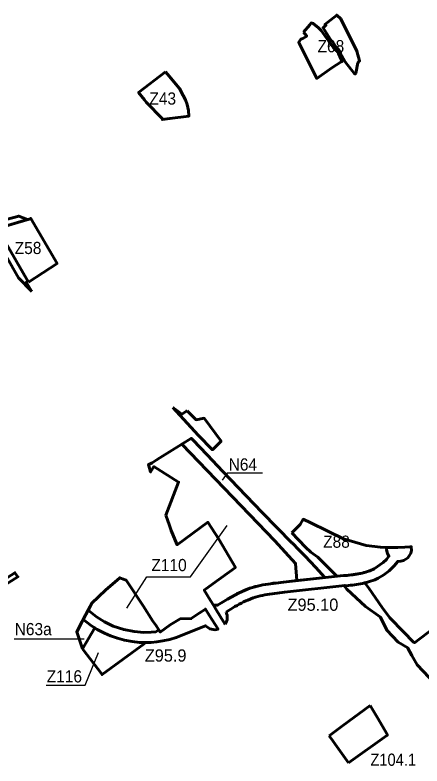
# Model space of a CAD drawing. Extents: x -650277 to -643420, y -1073980 to -1066720.
# Drawn here: x -647523 to -646722, y -1072547 to -1071070 of the extents above; entities that cross this region are included whole.
import ezdxf

# ---------------------------------------------------------------- set-up
doc = ezdxf.new("R2010")
doc.units = 0
doc.header["$LTSCALE"] = 9.6
for name, color, linetype, lineweight in [('15', 7, 'Continuous', 60), ('24', 7, 'Continuous', 60), ('30', 7, 'Continuous', 60), ('35', 7, 'Continuous', 60), ('42', 7, 'Continuous', 60), ('45', 7, 'Continuous', 60), ('60', 7, 'Continuous', 60), ('63', 7, 'Continuous', 25), ('9', 7, 'Continuous', 60)]:
    doc.layers.add(name, color=color, linetype=linetype, lineweight=lineweight)

msp = doc.modelspace()

# ---------------------------------------------------------------- linework, layer by layer
at = {"layer": '15'}
for points in [[(-647498.271, -1071593.544), (-647558.654, -1071489.738), (-647498.8, -1071471.94), (-647515.87, -1071465.25), (-647576.471, -1071481.091), (-647568.35, -1071496.656), (-647516.376, -1071586.89), (-647490.561, -1071613.609)], [(-647490.561, -1071613.609), (-647493.6, -1071608.5), (-647501.11, -1071595.45), (-647498.271, -1071593.544)]]:
    msp.add_lwpolyline(points, dxfattribs=at)
at = {"layer": '24'}
for points in [[(-647226.41, -1072054.11), (-647219.64, -1072074.29), (-647216.23, -1072084.14), (-647204.78, -1072110.92), (-647204.38, -1072111.87), (-647143.76, -1072067.69), (-647122.33, -1072101.34), (-647089.54, -1072156.53), (-647134.17, -1072188.95), (-647151.05, -1072201.21), (-647138.65, -1072221.5), (-647133, -1072230.754), (-647124.81, -1072231.168), (-647104.989, -1072219.005), (-647082.249, -1072206.591), (-647060.973, -1072197.439), (-647035.515, -1072191.104), (-647010.148, -1072187.308), (-646995.137, -1072185.597), (-646968.503, -1072182.672), (-646971.283, -1072148.82), (-647011.762, -1072104.502), (-647194.903, -1071913.941), (-647238.1, -1071941), (-647245.71, -1071945.77), (-647253.67, -1071950.76), (-647261.12, -1071954.82), (-647259.7, -1071957.06), (-647256.53, -1071968.64), (-647253.85, -1071964.38), (-647249.92, -1071958.12), (-647201.53, -1071988.71)], [(-647390.58, -1072316.75), (-647366.505, -1072275.41), (-647372.858, -1072271.363), (-647383.813, -1072263.219), (-647389.072, -1072258.845), (-647391.3, -1072263.04), (-647401.88, -1072283.4)], [(-647390.58, -1072316.75), (-647351.86, -1072367.52), (-647269.52, -1072307.17), (-647265.793, -1072304.439), (-647271.395, -1072304.452), (-647278.108, -1072304.147), (-647292.715, -1072302.646), (-647308.157, -1072299.786), (-647321.953, -1072296.073), (-647335.382, -1072291.341), (-647347.369, -1072286.111), (-647361.521, -1072278.584), (-647366.505, -1072275.41)]]:
    msp.add_lwpolyline(points, close=True, dxfattribs=at)
msp.add_arc((-646767.624, -1072120.384), 24.428, 264.28146, 264.89913, dxfattribs=at)
at = {"layer": '30'}
for points in [[(-646824.42, -1072428.58), (-646878.91, -1072468.54), (-646905.18, -1072487.8)], [(-646867.283, -1072540.984), (-646791.569, -1072487.198), (-646790.354, -1072486.136), (-646810.77, -1072451.09), (-646824.42, -1072428.58)], [(-646905.18, -1072487.8), (-646898.1, -1072498.02), (-646893.64, -1072504.45), (-646867.283, -1072540.984)]]:
    msp.add_lwpolyline(points, dxfattribs=at)
at = {"layer": '35'}
msp.add_lwpolyline([(-647246.563, -1072270.214), (-647251.85, -1072262.12), (-647271.38, -1072232.23), (-647304.32, -1072181.81), (-647310.33, -1072179.58), (-647317.33, -1072176.99), (-647345.42, -1072201.58), (-647372.1, -1072226.89), (-647375.551, -1072233.387), (-647379.422, -1072240.675), (-647363.317, -1072253.632), (-647347.382, -1072263.623), (-647330.032, -1072271.935), (-647309.416, -1072278.875), (-647288.769, -1072283.003), (-647269.579, -1072284.489), (-647255.671, -1072284.192), (-647246.206, -1072283.328), (-647240.55, -1072279.42)], close=True, dxfattribs=at)
at = {"layer": '42'}
msp.add_lwpolyline([(-647011.762, -1072104.502), (-646971.283, -1072148.82), (-646968.503, -1072182.672), (-646942.928, -1072179.864), (-646913.373, -1072176.618), (-646931.653, -1072156.802), (-646942.78, -1072144.74), (-646952.48, -1072134.22), (-646964.8, -1072121.83), (-646977.59, -1072108.96), (-646978.45, -1072108.09), (-647036.8, -1072048.41), (-647068.31, -1072015.68), (-647114.59, -1071967.77), (-647145.38, -1071935), (-647173.14, -1071905.45), (-647174.57, -1071904.06), (-647176.32, -1071902.3), (-647194.903, -1071913.941)], close=True, dxfattribs=at)
msp.add_lwpolyline([(-647637.082, -1072251.377), (-647611.306, -1072234.563), (-647589.02, -1072219.66), (-647517.51, -1072174.98), (-647523.71, -1072167.071), (-647616.719, -1072226.154), (-647642.504, -1072242.974), (-647800.2, -1072343.615)], dxfattribs=at)
at = {"layer": '45'}
msp.add_lwpolyline([(-646643.55, -1072233.5), (-646737.449, -1072305.019), (-646738.951, -1072303.49), (-646758.684, -1072283.41), (-646785.958, -1072255.505), (-646800.76, -1072235.668), (-646826.893, -1072197.582), (-646832.718, -1072189.697), (-646834.279, -1072186.818), (-646833.373, -1072186.562), (-646835.538, -1072187.097), (-646839.556, -1072187.988), (-646843.569, -1072188.789), (-646847.575, -1072189.507), (-646851.567, -1072190.155), (-646855.545, -1072190.741), (-646859.506, -1072191.276), (-646863.448, -1072191.771), (-646867.371, -1072192.234), (-646871.271, -1072192.675), (-646874.517, -1072192.471), (-646875.509, -1072192.58), (-646870.21, -1072199.51), (-646833.75, -1072233.32), (-646803.98, -1072254.74), (-646791.59, -1072279.78), (-646769.24, -1072303.65), (-646750.58, -1072315.02), (-646750.12, -1072315.82), (-646742.32, -1072329.62), (-646731.82, -1072348.2), (-646696.83, -1072385.81)], dxfattribs=at)
at = {"layer": '60'}
msp.add_line((-646978.602, -1072088.66), (-646951.95, -1072116.84), dxfattribs=at)
for points in [[(-647184.81, -1071848.61), (-647185.62, -1071849.12), (-647194.96, -1071854.93), (-647205.62, -1071847.24), (-647212.66, -1071842.15)], [(-647212.66, -1071842.15), (-647163.08, -1071896.13), (-647135.015, -1071925.145), (-647135.015, -1071925.145)], [(-647135.015, -1071925.145), (-647135.015, -1071925.145), (-647117.709, -1071908.3), (-647151.07, -1071863.08), (-647167.15, -1071866.22), (-647184.81, -1071848.61)], [(-646790.432, -1072129.195), (-646791.977, -1072122.305), (-646791.84, -1072117.172), (-646804.27, -1072116.98), (-646832.01, -1072113.66), (-646876.83, -1072100.12), (-646941.054, -1072069.172), (-646956.04, -1072061.95), (-646962.041, -1072072.379), (-646978.602, -1072088.66)], [(-646951.95, -1072116.84), (-646941.45, -1072126.84), (-646927.14, -1072136.74), (-646891.05, -1072172.79), (-646890.044, -1072174.056), (-646876.712, -1072172.592), (-646873.495, -1072172.799), (-646862.09, -1072171.444), (-646840.102, -1072167.623), (-646825.169, -1072163.164), (-646816.74, -1072159.571), (-646799, -1072147), (-646792.58, -1072140.847), (-646787.481, -1072134.643), (-646790.432, -1072129.195)], [(-646816.74, -1072159.571), (-646799, -1072147), (-646792.58, -1072140.847), (-646787.481, -1072134.643), (-646790.343, -1072129.36), (-646791.977, -1072122.305), (-646791.84, -1072117.172), (-646783.449, -1072117.302), (-646769.668, -1072117.517), (-646756.298, -1072117), (-646746.547, -1072116.221), (-646743.596, -1072115.985), (-646743.411, -1072123.612), (-646744.554, -1072128.415), (-646747.39, -1072134.069), (-646750.164, -1072137.467), (-646753.929, -1072140.612), (-646758.736, -1072143.137), (-646763.959, -1072144.535), (-646770.057, -1072144.677), (-646777.129, -1072153.576), (-646787.223, -1072163.402), (-646797.713, -1072171.151), (-646808.466, -1072177.78)], [(-647124.81, -1072231.168), (-647113.646, -1072224.274), (-647109.342, -1072221.634), (-647104.989, -1072219.005), (-647100.583, -1072216.405), (-647096.114, -1072213.845), (-647091.574, -1072211.346), (-647086.955, -1072208.921), (-647082.249, -1072206.591), (-647077.456, -1072204.373), (-647072.72, -1072202.352), (-647060.973, -1072197.439), (-647055.906, -1072195.893), (-647050.82, -1072194.5), (-647045.722, -1072193.245), (-647040.618, -1072192.117), (-647035.515, -1072191.104), (-647030.417, -1072190.192), (-647025.33, -1072189.37), (-647020.254, -1072188.623), (-647015.192, -1072187.939), (-647010.148, -1072187.308), (-647005.124, -1072186.715), (-647000.12, -1072186.148), (-646995.137, -1072185.597), (-646876.712, -1072172.592), (-646873.495, -1072172.799), (-646869.667, -1072172.366), (-646865.866, -1072171.917), (-646862.09, -1072171.444), (-646858.343, -1072170.937), (-646854.627, -1072170.389), (-646850.941, -1072169.791), (-646847.291, -1072169.137), (-646843.678, -1072168.416), (-646840.102, -1072167.623), (-646836.573, -1072166.751), (-646833.091, -1072165.791), (-646829.66, -1072164.739), (-646826.287, -1072163.588), (-646822.975, -1072162.332), (-646819.733, -1072160.968), (-646816.74, -1072159.571)], [(-646808.466, -1072177.78), (-646811.621, -1072179.254), (-646815.549, -1072180.906), (-646819.509, -1072182.408), (-646823.496, -1072183.769), (-646827.501, -1072184.997), (-646831.517, -1072186.103), (-646835.538, -1072187.097), (-646839.556, -1072187.988), (-646843.569, -1072188.789), (-646847.575, -1072189.507), (-646851.567, -1072190.155), (-646855.545, -1072190.741), (-646859.506, -1072191.276), (-646863.448, -1072191.771), (-646867.371, -1072192.234), (-646871.271, -1072192.675), (-646874.517, -1072192.471), (-646992.937, -1072205.475), (-646997.894, -1072206.024), (-647002.826, -1072206.583), (-647007.734, -1072207.162), (-647012.612, -1072207.773), (-647017.46, -1072208.427), (-647022.278, -1072209.136), (-647027.061, -1072209.91), (-647031.807, -1072210.758), (-647036.512, -1072211.693), (-647041.174, -1072212.723), (-647045.786, -1072213.858), (-647050.344, -1072215.107), (-647054.841, -1072216.479), (-647064.868, -1072220.746), (-647069.33, -1072222.651), (-647073.611, -1072224.631), (-647077.867, -1072226.739), (-647082.102, -1072228.962), (-647086.322, -1072231.285), (-647090.531, -1072233.695), (-647094.737, -1072236.177), (-647098.944, -1072238.718), (-647103.164, -1072241.306), (-647108.131, -1072244.373)], [(-647109.812, -1072268.588), (-647110.55, -1072267.42), (-647119.07, -1072253.56), (-647128.07, -1072238.83), (-647133, -1072230.754)]]:
    msp.add_lwpolyline(points, dxfattribs=at)
msp.add_lwpolyline([(-647265.793, -1072304.439), (-647255.16, -1072304.123), (-647244.428, -1072303.192), (-647232.368, -1072301.4), (-647218.5, -1072298.335), (-647205.975, -1072294.599), (-647148.171, -1072271.47), (-647139.697, -1072277.484), (-647130.12, -1072279.44), (-647123.774, -1072277.899), (-647141.05, -1072250.54), (-647148.71, -1072238.76), (-647148.71, -1072238.76), (-647160.91, -1072246.82), (-647176.7, -1072257.24), (-647198.3, -1072258.09), (-647218.35, -1072269.67), (-647237.6, -1072283.78), (-647240.55, -1072279.42), (-647246.206, -1072283.328), (-647255.671, -1072284.192), (-647269.579, -1072284.489), (-647288.769, -1072283.003), (-647309.416, -1072278.875), (-647330.032, -1072271.935), (-647347.382, -1072263.623), (-647363.317, -1072253.632), (-647379.422, -1072240.675), (-647389.072, -1072258.845), (-647383.813, -1072263.219), (-647372.858, -1072271.363), (-647361.521, -1072278.584), (-647347.369, -1072286.111), (-647335.382, -1072291.341), (-647321.953, -1072296.073), (-647308.157, -1072299.786), (-647292.715, -1072302.646), (-647278.108, -1072304.147), (-647271.395, -1072304.452), (-647265.793, -1072304.439)], close=True, dxfattribs=at)
for start, end in [(77.44425, 96.77054), (326.23773, 25.81772)]:
    msp.add_arc((-647130.12, -1072255.012), 24.428, start, end, dxfattribs=at)
at = {"layer": '63'}
msp.add_line((-647525, -1072297), (-647387, -1072297), dxfattribs=at)
for points in [[(-647036, -1071971), (-647106, -1071971), (-647116, -1071985)], [(-647303, -1072237), (-647264, -1072175), (-647178, -1072175), (-647106, -1072074)], [(-647462, -1072388), (-647385, -1072388), (-647359, -1072324)]]:
    msp.add_lwpolyline(points, dxfattribs=at)
at = {"layer": '9'}
for points in [[(-646881.89, -1071077.03), (-646890.12, -1071069.67), (-646913.49, -1071088.22), (-646911.58, -1071089.9), (-646917.04, -1071094.75), (-646910.53, -1071105.18), (-646902.62, -1071117.58), (-646895.56, -1071126.84), (-646892.339, -1071131.481), (-646886.78, -1071137.25), (-646882.37, -1071143.39), (-646883.63, -1071144.15), (-646873.89, -1071161.58), (-646861.58, -1071177.05), (-646854.49, -1071185.87), (-646852.86, -1071183.98), (-646848.58, -1071163.95), (-646845.39, -1071159.98), (-646850.93, -1071140.54)], [(-646955.39, -1071103.23), (-646949.12, -1071111.22), (-646957.26, -1071115.61), (-646960.72, -1071117.25), (-646964.99, -1071123.18), (-646964.43, -1071125.3), (-646955.2, -1071143.67), (-646929.64, -1071194.58), (-646899.85, -1071173.89), (-646881.68, -1071161.83), (-646879.91, -1071161.24), (-646881.97, -1071155.84), (-646887.07, -1071145.66), (-646890.59, -1071140.39), (-646896.62, -1071133.93), (-646904.64, -1071123.54), (-646906.72, -1071120.46), (-646920.54, -1071099.98), (-646925.88, -1071094.68), (-646936.51, -1071086.33), (-646940.67, -1071085.15), (-646943.47, -1071088.69)], [(-647226.895, -1071181.511), (-647280.14, -1071221.92), (-647268.52, -1071236.78), (-647265.15, -1071241.1), (-647233.34, -1071274.07), (-647233.64, -1071275.42), (-647218.75, -1071273.32), (-647181.12, -1071268.66), (-647181.99, -1071257.66), (-647184.58, -1071245.67), (-647187.68, -1071236.74), (-647192.29, -1071228.1), (-647199.82, -1071213.98), (-647223.46, -1071185.83)], [(-647497.04, -1071595.66), (-647440.67, -1071558.93), (-647492.3, -1071470), (-647495.85, -1071471.06), (-647558.654, -1071489.738)]]:
    msp.add_lwpolyline(points, close=True, dxfattribs=at)

# ---------------------------------------------------------------- texts
at = {"layer": '63'}
for s, width, p in [('Z68', 0.95, (-646928, -1071143)), ('Z43', 0.95, (-647259, -1071246)), ('Z58', 0.95, (-647524, -1071540)), ('N64', 0.95, (-647103, -1071966)), ('Z88', 0.95, (-646917, -1072118)), ('Z110', 0.95, (-647255, -1072164)), ('N63a', 0.95, (-647524, -1072290)), ('Z116', 0.95, (-647461, -1072383)), ('Z104.1', 0.9, (-646824, -1072547))]:
    msp.add_text(s, height=24, dxfattribs=dict(at, width=width)).set_placement(p)
for s, p in [('Z95.10', (-646987, -1072242)), ('Z95.9', (-647268, -1072342))]:
    msp.add_text(s, height=24, dxfattribs=at).set_placement(p)

doc.saveas('drawing.dxf')
